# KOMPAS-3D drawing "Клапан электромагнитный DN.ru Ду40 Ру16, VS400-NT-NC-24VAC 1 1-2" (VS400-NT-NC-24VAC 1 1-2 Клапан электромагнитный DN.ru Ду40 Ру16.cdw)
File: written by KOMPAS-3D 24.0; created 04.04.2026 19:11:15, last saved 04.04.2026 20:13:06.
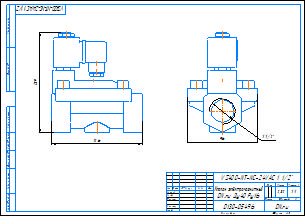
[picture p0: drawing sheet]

Document properties: c3d_UniqueCompID: ef56311e-7521-43dc-8291-0e6108b3d81d; Обозначение: VS400-ET-NC-220VAC 1; Наименование: Клапан электромагнитный DN.ru Ду25 Ру16; Автор: artio; Класс точности: c; Знак неуказанной шероховатости: Шероховатость не задана; Рассекать на разрезах: Да; c3d_UniqueCompID: ef56311e-7521-43dc-8291-0e6108b3d81d; Обозначение: VS400-ET-NC-220VAC 1-2; Наименование: Клапан электромагнитный DN.ru Ду15 Ру16; Автор: artio; Класс точности: c; Знак неуказанной шероховатости: Шероховатость не задана; Рассекать на разрезах: Да; c3d_UniqueCompID: ef56311e-7521-43dc-8291-0e6108b3d81d; Обозначение: VS400-ET-NC-220VAC 3-4; Наименование: Клапан электромагнитный DN.ru Ду20 Ру16; Автор: artio; Класс точности: c; Знак неуказанной шероховатости: Шероховатость не задана; Рассекать на разрезах: Да; c3d_UniqueCompID: ef56311e-7521-43dc-8291-0e6108b3d81d; Обозначение: VS400-ET-NC-220VAC 1 1-4; Наименование: Клапан электромагнитный DN.ru Ду32 Ру16; Автор: artio; Класс точности: c; Знак неуказанной шероховатости: Шероховатость не задана; Рассекать на разрезах: Да; c3d_UniqueCompID: ef56311e-7521-43dc-8291-0e6108b3d81d; Обозначение: VS400-ET-NC-220VAC 3-8; Наименование: Клапан электромагнитный DN.ru Ду10 Ру16; Автор: artio; Класс точности: c; Знак неуказанной шероховатости: Шероховатость не задана; Рассекать на разрезах: Да; c3d_UniqueCompID: ef56311e-7521-43dc-8291-0e6108b3d81d; Обозначение: VS400-ET-NC-220VAC 1 1-2; Наименование: Клапан электромагнитный DN.ru Ду40 Ру16; Автор: artio; Класс точности: c; Знак неуказанной шероховатости: Шероховатость не задана; Рассекать на разрезах: Да; Автор: artio; Форматы листов документа: A3; Полное имя файла: VS400-NT-NC-24VAC 1 1-2 Клапан электромагнитный DN.ru Ду40 Ру16.m3d; Масса: 2.321; Наименование: Клапан электромагнитный DN.ru Ду40 Ру16; Количество листов документа: 1; Примечание: D130-05496

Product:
- Body: Тело 1  | qty 1
    Масса: 4.144257
- Part/product: Клапан электромагнитный DN.ru Ду40 Ру16  | designation VS400-NT-NC-24VAC 1 1-2
    Масса: 2.321
    Раздел спецификации: Прочие изделия
    Примечание: D130-05496
    additional columns: ef56311e-7521-43dc-8291-0e6108b3d81d; VS400-ET-NC-220VAC 1 1-2; artio; c; Шероховатость не задана; Да

Views: Вид 1, Спереди
Referenced files in C:\Users\artio\OneDrive\Рабочий стол\Клапан электромагнитный DN.ru\VS400-ET-NC\VS400-ET-NC-24VDC\: VS400-ET-NC-24VDC 3-8 Клапан электромагнитный DN.ru Ду10 Ру16.m3d
Referenced files in C:\Users\artio\OneDrive\Рабочий стол\Клапан электромагнитный DN.ru\VS400-NT-NC\VS400-NT-NC-24VAC\: VS400-NT-NC-24VAC 1 1-2 Клапан электромагнитный DN.ru Ду40 Ру16.m3d
Referenced files in C:\Users\artio\OneDrive\Рабочий стол\Клапан электромагнитный DN.ru\VS400-ET-NC\: VS400-ET-NC-24VDC 3-8 Клапан электромагнитный DN.ru Ду10 Ру16.cdw
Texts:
  VS400-NT-NC-24VAC 1 1-2
  Клапан электромагнитный
  DN.ru Ду40 Ру16
  VS400-NT-NC-24VAC 1 1/2"
  VS400-NT-NC-24VAC 1 1/2"-
  Клапан электромагнитный DN.ru Ду40 Ру16
  VS400-NT-NC-24VAC 1 1-2 Клапан электромагнитный DN.ru Ду40 Ру16
Dimensions and other numbers on the sheet: 0; 3; 2; 4; 96; 1 1/2"; 1:1; 1; 2,32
